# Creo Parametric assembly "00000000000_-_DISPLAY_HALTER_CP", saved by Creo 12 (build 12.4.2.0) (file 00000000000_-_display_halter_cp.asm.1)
Units: Custom; MM, KILOGRAM, SECS

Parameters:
  PTC_WM_ITERATION = "0"
  PTC_WM_VERSION = "-.0"
  PTC_WM_LIFECYCLE_STATE = "In Work"
  PTC_WM_LIFECYCLE = "MO_CADDocument"
  PTC_WM_CREATED_BY = "Maximilian Roepper (Z0017RMS: MO)"
  PTC_WM_CREATED_ON = "18-Sep-26 11:36:42 AM"
  PTC_WM_MODIFIED_BY = "Maximilian Roepper (Z0017RMS: MO)"
  PTC_WM_MODIFIED_ON = "02-Oct-26 02:44:18 PM"
  PDMLINKNUMBER = "PDM000071454993"
  PTC_WM_NUMBER = "PDM000071454993"

Other parameters: WEIGHT, WEIGHT_FACTOR, WEIGHT_ADD, MC_ERRORS, SUPPLIER

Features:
  1. component "00000000000_-_DISPLAY_HALT_SKEL"
  2. coordinate system
  3. component "00000000000_-_GEH_DECKEL"
  4. component "1111111111_-_PLATINE_IMP"
  5. component "00000000000_-_GEH_KOERPER"
  6. component "TACTILE_SWITCH_3D_MODEL"

Other named items: DRW_VIEW_ORG, SIEMENS_MO, ROUGH-GROB, EXCLUDE_ALL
